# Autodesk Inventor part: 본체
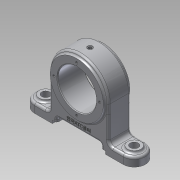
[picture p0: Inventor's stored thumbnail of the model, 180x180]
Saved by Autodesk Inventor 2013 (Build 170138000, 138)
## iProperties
Created: 2019-05
Part Number: 본체
Material: 알루미늄 6061
Document SubType Name: Modeling
Designer: Administrator
Mass: 456.252 g
Surface Area: 321.325 cm^2
Volume: 168.359 cm^3
Density: 2.71 g/cm^3
Author: Administrator
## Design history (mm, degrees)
sketch "스케치12"
  geometry: C1 r 40 at (0, 0); 1 further point
  constraints: 1 centre point, 1 coincident
  dimensions: "d55" = 80 diameter of C1
extrude "돌출9" new body sketch "스케치12" stored distance "d57" = 30; taper "d58" = 0 deg
sketch "스케치13"
  geometry: C1 r 36 at (0, 0); 1 further point
  constraints: 1 centre point, 1 coincident
  dimensions: "d59" = 72 diameter of C1
extrude "돌출10" join sketch "스케치13" stored distance "d61" = 36; taper "d62" = 0 deg
sketch "스케치14"
  geometry: C1 r 36 at (0, 0) reference; C2 r 26 at (0, 0)
  constraints: 1 centre point, 1 coincident
  dimensions: "d63" = 52 diameter of C2
extrude "돌출11" cut sketch "스케치14" stored distance "d65" = 36; taper "d66" = 0 deg
sketch "스케치15"
  geometry: L1 (-40, 0)-(-40, -48); L2 (40, 0)-(40, -48); L3 (-40, -48)-(-75, -48); L4 (-75, -48)-(-75, -60); L5 (-75, -60)-(-36, -60); L6 (-36, -60)-(-36, -56); L7 (-36, -56)-(-30, -56); L8 (-30, -56)-(-30, -50); L9 (-30, -50)-(30, -50); L10 (30, -50)-(30, -56); L11 (30, -56)-(36, -56); L12 (36, -56)-(36, -60); L13 (36, -60)-(75, -60); L14 (75, -60)-(75, -48); L15 (75, -48)-(40, -48); A1 r 40 centre (0, 0) between (-40, 0) and (40, 0) reference; 1 further point
  constraints: 30 end point, 8 vertical, 7 horizontal, 3 collinear, 2 point on circle, 2 tangent
  dimensions: "d67" = 150 distance between parallel lines of L14 L4; "d69" = 12 distance between parallel lines of L3 L5; "d70" = 4 distance between parallel lines of L5 L7; "d71" = 10 distance between parallel lines of L5 L9; "d72" = 36 distance from line of point (0, 0) L6; "d73" = 30 distance from line of point (0, 0) L8; "d74" = 60 distance from line of L5 point (0, 0); "d75" = 60 distance between parallel lines of L10 L8; "d76" = 72 distance between parallel lines of L6 L12; "d77" = 75 distance from line of point (0, 0) L14
extrude "돌출12" join sketch "스케치15" stored distance "d78" = 30; taper "d79" = 0 deg
sketch "스케치16"
  geometry: C1 r 26 at (0, 0) reference; 1 further point
  constraints: 1 vertical alignment
  dimensions: "d80" = 31 distance of C1.centre point (0, 31)
hole "구멍2" sketch "스케치16" at (0, 31) diameter "d81" = 3.242; stored, may be unused: countersink angle "d85" = 90 deg, drill point angle "d87" = 118 deg; dims "d82" = 6, "d83" = 4, "d84" = 2, "d86" = 8
sketch "스케치17"
  geometry: C1 r 1.5 at (0, 26); 1 further point
  constraints: 2 vertical alignment, 1 centre point, 1 other
  dimensions: "d91" = 3 diameter of C1
extrude "돌출13" cut sketch "스케치17" stored distance "d93" = 30; taper "d94" = 0 deg
node "작업 평면3"
sketch "스케치18"
  geometry: C1 r 3.5 at (0, 0); 1 further point
  constraints: 1 centre point, 1 coincident
  dimensions: "d96" = 7 diameter of C1
extrude "돌출14" cut sketch "스케치18" distance "d98" = 1; taper "d99" = 0 deg
sketch "스케치19"
  geometry: C1 r 3.5 at (0, 0) reference; 1 further point
  constraints: 1 coincident
hole "구멍3" sketch "스케치19" at (0, 0) diameter "d100" = 4.917; stored, may be unused: countersink angle "d104" = 90 deg, drill point angle "d106" = 118 deg; dims "d101" = 7, "d102" = 4, "d103" = 2, "d105" = 9
sketch "스케치20"
  geometry: L1 (-30, -50)-(30, -50) reference; C1 r 36 at (0, 0) reference; 1 further point
  constraints: 1 vertical alignment, 1 other
  dimensions: "d107" = 7 distance from line of L1 point (0, -43)
feature "엠보싱1" sketch "스케치20" dims "d108" = 0.5, "d109" = 0
fillet "모깎기1" dims "d110" = 6
sketch "스케치21"
  geometry: C1 r 9 at (15, 15); 1 further point
  constraints: 1 centre point, 1 horizontal alignment
  dimensions: "d111" = 18 diameter of C1; "d113" = 60 distance of point (75, 15) C1.centre
extrude "돌출15" join sketch "스케치21" distance "d114" = 3; taper "d115" = 0 deg
hole "구멍4" diameter "d118" = 11; stored, may be unused: countersink angle "d122" = 90 deg, drill point angle "d124" = 118 deg; dims "d116" = 10, "d117" = 10, "d119" = 8, "d120" = 4, "d121" = 2, "d123" = 10
fillet "모깎기2" dims "d125" = 3
fillet "모깎기4" dims "d127" = 3
fillet "모깎기5" dims "d128" = 15
fillet "모깎기7" dims "d130" = 3
fillet "모깎기6" dims "d129" = 3
chamfer "모따기1" distance "d131" = 1; stored, may be unused: second distance "d132" = 2, angle "d133" = 45 deg
fillet "모깎기8" dims "d136" = 3
hole "구멍5" diameter "d140" = 2; stored, may be unused: countersink angle "d144" = 90 deg, drill point angle "d146" = 118 deg; dims "d138" = 10, "d139" = 10, "d141" = 6, "d142" = 4, "d143" = 2, "d145" = 14
node "솔리드3"
pattern_circular "원형 패턴2" dims angle "d89" = 360 deg
mirror "대칭1"
mirror "대칭2"
